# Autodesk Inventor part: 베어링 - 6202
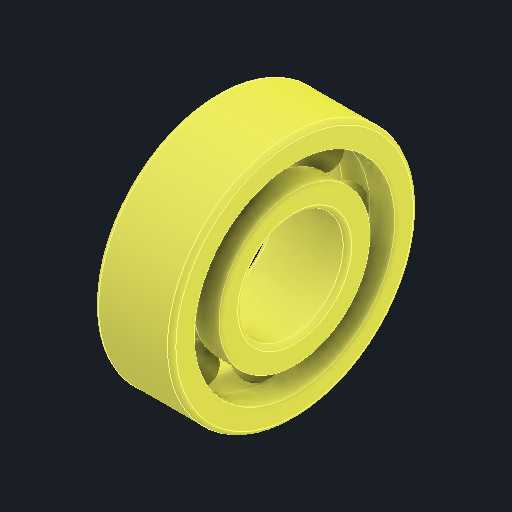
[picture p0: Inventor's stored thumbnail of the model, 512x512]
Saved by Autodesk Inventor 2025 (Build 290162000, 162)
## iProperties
Created: 2025-08
Part Number: 베어링 - 6202
Material: 강, 연강
Description: 깊은 그루브 볼 베어링
Document SubType Name: Modeling
Designer: infra012
Density: 7.86 g/cm^3
Appearance: 기본값
Author: jhkim
Sending System: Autodesk Inventor 2026
Preprocessor: ST-DEVELOPER v20.1
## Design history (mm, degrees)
sketch "스케치1"
  geometry: 1 further point
feature "Solid1"
feature "Solid1:1"
feature "Solid1:2"
feature "Solid1:3"
feature "Solid1:4"
feature "Solid1:5"
feature "Solid1:6"
feature "Solid1:7"
feature "Solid1:8"
feature "Solid1:9"
node "솔리드1"
node "솔리드2"
node "솔리드3"
node "솔리드4"
node "솔리드5"
node "솔리드6"
node "솔리드7"
node "솔리드8"
node "솔리드9"
node "솔리드10"
